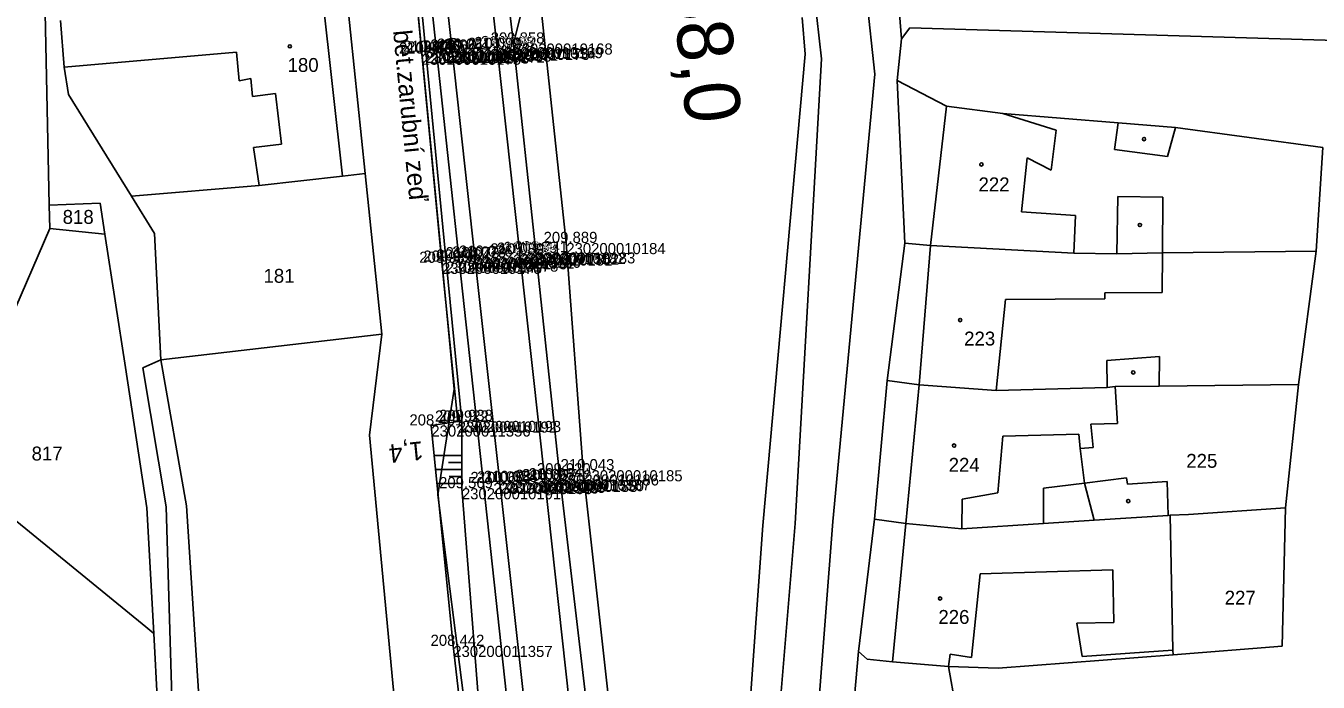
# Model space of a CAD drawing. Extents: x -563148 to -561712, y -1182311 to -1179502.
# Drawn here: x -562725.1 to -562585.8, y -1180251.7 to -1180180.9 of the extents above; entities that cross this region are included whole.
import ezdxf

# ---------------------------------------------------------------- set-up
doc = ezdxf.new("R2010")
doc.units = 0
for name, color, linetype in [('Vrstva 1', 7, 'Continuous'), ('Vrstva 13', 7, 'Continuous'), ('Vrstva 4', 7, 'Continuous'), ('Vrstva 48', 7, 'Continuous'), ('Vrstva 49', 7, 'Continuous'), ('Vrstva 53', 7, 'Continuous'), ('Vrstva 55', 7, 'Continuous'), ('Vrstva 56', 7, 'Continuous'), ('Vrstva 57', 7, 'Continuous'), ('Vrstva 60', 7, 'Continuous'), ('Vrstva 61', 7, 'Continuous'), ('Vrstva 7', 7, 'Continuous')]:
    doc.layers.add(name, color=color, linetype=linetype)

msp = doc.modelspace()

# ---------------------------------------------------------------- linework, layer by layer
at = {"layer": 'Vrstva 1'}
for points in [[(-562689.44, -1180090.3), (-562686.84, -1180113.86), (-562684.3, -1180136.88), (-562682.8, -1180150.56), (-562681.89, -1180158.81), (-562679.16, -1180183.55), (-562676.7, -1180205.89), (-562674.02, -1180230.17), (-562671.32, -1180254.48), (-562668.19, -1180282.59), (-562665.59, -1180304.98), (-562662.34, -1180329.4), (-562657.66, -1180357.66), (-562652.65, -1180381.24), (-562646.28, -1180405.63), (-562637.05, -1180434.8), (-562628.49, -1180458.75), (-562620.52, -1180479.9), (-562613.35, -1180498.59), (-562605.09, -1180520.3), (-562597.15, -1180542.18)], [(-562684.6, -1180089.77), (-562682.01, -1180113.42), (-562679.52, -1180136.02), (-562677.96, -1180150.24), (-562677.07, -1180158.3), (-562674.32, -1180183.28), (-562671.87, -1180205.48), (-562669.18, -1180229.92), (-562666.55, -1180253.83), (-562663.38, -1180282.45), (-562660.88, -1180304.41), (-562657.73, -1180328.53), (-562653.09, -1180356.9), (-562648.14, -1180380.43), (-562641.99, -1180404.16), (-562632.84, -1180433.4), (-562624.35, -1180457.45), (-562616.4, -1180478.66), (-562609.26, -1180497.36), (-562601.11, -1180519.01), (-562593.2, -1180541.01)]]:
    msp.add_lwpolyline(points, dxfattribs=at)
at = {"layer": 'Vrstva 13'}
msp.add_lwpolyline([(-562684.35, -1180163.85), (-562683.9, -1180163.81), (-562682, -1180183.68), (-562679.82, -1180206.34), (-562678.12, -1180223.53), (-562678.56, -1180223.6), (-562680.26, -1180206.46), (-562682.44, -1180183.89), (-562684.35, -1180163.85)], dxfattribs=at)
at = {"layer": 'Vrstva 4'}
for points in [[(-562627.68, -1180467.38), (-562628.18, -1180466.77), (-562631.27, -1180459.35), (-562639.19, -1180435.74), (-562648.5, -1180405.64), (-562654.42, -1180382.81), (-562656.87, -1180370.73), (-562659.41, -1180357.99), (-562663.15, -1180335.73), (-562663.92, -1180330.37), (-562667.29, -1180305.3), (-562668.45, -1180295.93), (-562670.31, -1180282.9), (-562673.11, -1180254.81), (-562678.42, -1180206.22), (-562683.27, -1180161.19)], [(-562675.28, -1180160.14), (-562672.56, -1180182.79), (-562670.12, -1180205.33), (-562667.57, -1180229.29), (-562664.72, -1180253.74), (-562661.63, -1180281.88), (-562659.7, -1180289.08), (-562659.83, -1180291.12), (-562660.13, -1180295.12), (-562659.09, -1180304.26), (-562655.97, -1180328.16), (-562655.07, -1180334.5), (-562651.3, -1180356.53), (-562648.06, -1180373.04), (-562645.81, -1180378.74), (-562644.11, -1180383.05), (-562645, -1180383.36), (-562644.89, -1180383.72), (-562638.04, -1180407.02), (-562630.41, -1180432), (-562621.94, -1180456.49), (-562617.79, -1180466.85), (-562617.96, -1180467.57)]]:
    msp.add_lwpolyline(points, dxfattribs=at)
at = {"layer": 'Vrstva 48'}
for p, q in [((-562678.12, -1180227.27), (-562681.09, -1180227.27)), ((-562678.11, -1180228.02), (-562679.56, -1180228.02)), ((-562678.11, -1180228.77), (-562680.94, -1180228.77)), ((-562678.11, -1180229.52), (-562679.49, -1180229.52)), ((-562678.11, -1180230.27), (-562680.79, -1180230.27))]:
    msp.add_line(p, q, dxfattribs=at)
at = {"layer": 'Vrstva 49'}
for points in [[(-562670.19, -1180173.32), (-562672.56, -1180182.79), (-562670.12, -1180205.33), (-562667.57, -1180229.29), (-562664.72, -1180253.74), (-562661.63, -1180281.88), (-562659.7, -1180289.08), (-562659.7, -1180284.87), (-562657.76, -1180284.63), (-562657.19, -1180284.56), (-562657.98, -1180289.86), (-562658.29, -1180294.94), (-562656.62, -1180309.12), (-562654.27, -1180327.97), (-562652.88, -1180336.21), (-562648.73, -1180360.23), (-562646.24, -1180372.8), (-562644.28, -1180378.23), (-562642.51, -1180382.83), (-562642.26, -1180382.67)], [(-562670.19, -1180173.32), (-562666.85, -1180204.32), (-562665.02, -1180228.85), (-562662.19, -1180254.41), (-562657.94, -1180278.46), (-562656.85, -1180284.3), (-562656.21, -1180288), (-562655.39, -1180309.06), (-562651.1, -1180335.95), (-562646.99, -1180359.71), (-562648.73, -1180360.23)], [(-562656.73, -1180384.82), (-562658.28, -1180387.39), (-562659.09, -1180377.63), (-562662.6, -1180359.66), (-562666.24, -1180337.23), (-562668.61, -1180323.67), (-562671.72, -1180306.26), (-562674.41, -1180286.66), (-562676.53, -1180269.62), (-562679.04, -1180247.81), (-562681.41, -1180224.02), (-562678.56, -1180223.6)], [(-562678.12, -1180223.53), (-562678.11, -1180230.79), (-562676.2, -1180255.01), (-562672.73, -1180283.26), (-562672.48, -1180286.15), (-562672.4, -1180289.22), (-562670.02, -1180305.33), (-562667.54, -1180323.34), (-562664.87, -1180336.93), (-562661.11, -1180359.14), (-562658.61, -1180370.38), (-562657.79, -1180380.81), (-562657.06, -1180381.08), (-562656.73, -1180384.82)]]:
    msp.add_lwpolyline(points, dxfattribs=at)
at = {"layer": 'Vrstva 53'}
for p, q in [((-562684.1, -1180166.53), (-562678.95, -1180220.12)), ((-562641.4, -1180179.98), (-562641.09, -1180183.95)), ((-562645.64, -1180234.81), (-562641.09, -1180183.95)), ((-562678.95, -1180220.12), (-562680.72, -1180231.5)), ((-562680.72, -1180231.5), (-562673.43, -1180288.54)), ((-562651.13, -1180311.38), (-562645.64, -1180234.81))]:
    msp.add_line(p, q, dxfattribs=at)
at = {"layer": 'Vrstva 55'}
for p, q in [((-562631.58, -1180171.07), (-562630.71, -1180182.3)), ((-562723.22, -1180171.35), (-562722.61, -1180200.26)), ((-562688.54, -1180196.82), (-562690.59, -1180177.1)), ((-562721.4, -1180180.3), (-562721, -1180185.34)), ((-562630.71, -1180182.3), (-562631.16, -1180186.8)), ((-562721, -1180185.34), (-562720.53, -1180188.31)), ((-562631.16, -1180186.8), (-562630.35, -1180204.35)), ((-562625.86, -1180189.56), (-562631.16, -1180186.8)), ((-562720.53, -1180188.31), (-562713.76, -1180199.28)), ((-562627.58, -1180204.6), (-562625.86, -1180189.56)), ((-562619.76, -1180190.34), (-562625.86, -1180189.56)), ((-562607.34, -1180191.36), (-562619.76, -1180190.34)), ((-562601.16, -1180191.87), (-562607.34, -1180191.36)), ((-562585.25, -1180194.02), (-562601.16, -1180191.87)), ((-562585.25, -1180194.02), (-562585.97, -1180205.19)), ((-562691, -1180197.1), (-562699.98, -1180198.11)), ((-562688.54, -1180196.82), (-562691, -1180197.1)), ((-562686.74, -1180214.17), (-562688.54, -1180196.82)), ((-562699.98, -1180198.11), (-562713.76, -1180199.28)), ((-562717.12, -1180200.03), (-562722.61, -1180200.26)), ((-562722.61, -1180200.26), (-562722.56, -1180202.76)), ((-562716.61, -1180203.39), (-562717.12, -1180200.03)), ((-562713.76, -1180199.28), (-562711.28, -1180203.29)), ((-562722.56, -1180202.76), (-562726.91, -1180212.84)), ((-562722.56, -1180202.76), (-562716.61, -1180203.39)), ((-562711.28, -1180203.29), (-562710.59, -1180216.93)), ((-562714.4, -1180217.76), (-562716.61, -1180203.39)), ((-562630.35, -1180204.35), (-562632.25, -1180219.16)), ((-562628.78, -1180219.62), (-562627.58, -1180204.6)), ((-562612.1, -1180205.44), (-562627.58, -1180204.6)), ((-562607.47, -1180205.48), (-562612.1, -1180205.44)), ((-562602.56, -1180205.39), (-562607.47, -1180205.48)), ((-562585.97, -1180205.19), (-562602.56, -1180205.39)), ((-562585.97, -1180205.19), (-562587.88, -1180219.6)), ((-562710.59, -1180216.93), (-562686.74, -1180214.17)), ((-562688.08, -1180225.06), (-562686.74, -1180214.17)), ((-562710.59, -1180216.93), (-562712.54, -1180217.8)), ((-562707.83, -1180232.69), (-562710.59, -1180216.93)), ((-562712.08, -1180232.92), (-562714.4, -1180217.76)), ((-562712.54, -1180217.8), (-562710.02, -1180232.81)), ((-562632.25, -1180219.16), (-562633.62, -1180234.15)), ((-562630.24, -1180234.62), (-562628.78, -1180219.62)), ((-562620.5, -1180220.25), (-562628.78, -1180219.62)), ((-562608.51, -1180219.94), (-562620.5, -1180220.25)), ((-562607.66, -1180219.82), (-562608.51, -1180219.94)), ((-562602.9, -1180219.79), (-562607.66, -1180219.82)), ((-562607.66, -1180219.82), (-562607.4, -1180223.8)), ((-562587.88, -1180219.6), (-562602.9, -1180219.79)), ((-562587.88, -1180219.6), (-562589.27, -1180232.92)), ((-562607.4, -1180223.8), (-562610.29, -1180223.88)), ((-562610.29, -1180223.88), (-562610.01, -1180226.39)), ((-562683.82, -1180270.34), (-562688.08, -1180225.06)), ((-562610.01, -1180226.39), (-562611.42, -1180226.52)), ((-562611.42, -1180226.52), (-562610.96, -1180230.24)), ((-562734.28, -1180227.74), (-562712.2, -1180245.77)), ((-562610.96, -1180230.24), (-562606.42, -1180229.68)), ((-562606.42, -1180229.68), (-562606.31, -1180230.36)), ((-562606.31, -1180230.36), (-562602.04, -1180230.08)), ((-562602.04, -1180230.08), (-562601.92, -1180233.73)), ((-562711.35, -1180246.47), (-562712.08, -1180232.92)), ((-562710.02, -1180232.81), (-562709.35, -1180254.57)), ((-562706.44, -1180253.81), (-562707.83, -1180232.69)), ((-562601.92, -1180233.73), (-562609.91, -1180234.25)), ((-562601.72, -1180233.72), (-562601.92, -1180233.73)), ((-562599.75, -1180233.62), (-562601.72, -1180233.72)), ((-562601.72, -1180233.72), (-562601.42, -1180248.29)), ((-562589.27, -1180232.92), (-562599.75, -1180233.62)), ((-562589.27, -1180232.92), (-562589.65, -1180247.85)), ((-562633.62, -1180234.15), (-562635.33, -1180248.42)), ((-562631.66, -1180249.55), (-562630.24, -1180234.62)), ((-562624.18, -1180235.17), (-562630.24, -1180234.62)), ((-562615.39, -1180234.61), (-562624.18, -1180235.17)), ((-562609.91, -1180234.25), (-562615.39, -1180234.61)), ((-562712.2, -1180245.77), (-562711.35, -1180246.47)), ((-562710.94, -1180254.02), (-562711.35, -1180246.47)), ((-562589.65, -1180247.85), (-562601.41, -1180248.77)), ((-562635.33, -1180248.42), (-562637.31, -1180270.41)), ((-562601.41, -1180248.77), (-562620.28, -1180250.23)), ((-562601.42, -1180248.29), (-562601.41, -1180248.77)), ((-562625.64, -1180250.04), (-562631.66, -1180249.55)), ((-562625.64, -1180250.04), (-562624.86, -1180254.3)), ((-562620.28, -1180250.23), (-562625.64, -1180250.04))]:
    msp.add_line(p, q, dxfattribs=at)
at = {"layer": 'Vrstva 56'}
for p, q in [((-562640.31, -1180124.15), (-562633.56, -1180186.11)), ((-562639.33, -1180184.45), (-562645.98, -1180126.03)), ((-562693.17, -1180177.53), (-562691, -1180197.1)), ((-562630.71, -1180182.3), (-562629.81, -1180181.11)), ((-562629.81, -1180181.11), (-562579.88, -1180182.58)), ((-562702.43, -1180183.72), (-562721, -1180185.34)), ((-562702.15, -1180186.81), (-562702.43, -1180183.72)), ((-562639.33, -1180184.45), (-562642.18, -1180234.62)), ((-562700.87, -1180186.58), (-562702.15, -1180186.81)), ((-562700.7, -1180188.53), (-562700.87, -1180186.58)), ((-562638.1, -1180234.39), (-562633.56, -1180186.11)), ((-562698.2, -1180188.19), (-562700.7, -1180188.53)), ((-562697.58, -1180193.66), (-562698.2, -1180188.19)), ((-562619.76, -1180190.34), (-562614, -1180192.14)), ((-562614, -1180192.14), (-562614.55, -1180196.45)), ((-562607.72, -1180194.22), (-562607.34, -1180191.36)), ((-562601.16, -1180191.87), (-562602.01, -1180194.99)), ((-562700.58, -1180194), (-562697.58, -1180193.66)), ((-562699.98, -1180198.11), (-562700.58, -1180194)), ((-562602.01, -1180194.99), (-562607.72, -1180194.22)), ((-562617.15, -1180195.14), (-562617.76, -1180200.95)), ((-562614.55, -1180196.45), (-562617.15, -1180195.14)), ((-562607.47, -1180205.48), (-562607.38, -1180199.31)), ((-562607.38, -1180199.31), (-562602.51, -1180199.37)), ((-562602.51, -1180199.37), (-562602.56, -1180205.39)), ((-562617.76, -1180200.95), (-562611.93, -1180201.36)), ((-562611.93, -1180201.36), (-562612.1, -1180205.44)), ((-562630.35, -1180204.35), (-562627.58, -1180204.6)), ((-562602.56, -1180205.39), (-562602.59, -1180209.67)), ((-562602.59, -1180209.67), (-562608.76, -1180209.71)), ((-562608.76, -1180209.71), (-562608.76, -1180210.35)), ((-562619.47, -1180210.41), (-562620.5, -1180220.25)), ((-562608.76, -1180210.35), (-562619.47, -1180210.41)), ((-562608.55, -1180217.01), (-562602.86, -1180216.59)), ((-562608.51, -1180219.94), (-562608.55, -1180217.01)), ((-562602.86, -1180216.59), (-562602.9, -1180219.79)), ((-562632.25, -1180219.16), (-562628.78, -1180219.62)), ((-562619.76, -1180225.16), (-562620.32, -1180231.31)), ((-562611.57, -1180224.97), (-562619.76, -1180225.16)), ((-562611.42, -1180226.52), (-562611.57, -1180224.97)), ((-562615.39, -1180234.61), (-562615.37, -1180230.8)), ((-562615.37, -1180230.8), (-562610.96, -1180230.24)), ((-562609.91, -1180234.25), (-562610.96, -1180230.24)), ((-562624.15, -1180231.97), (-562624.18, -1180235.17)), ((-562620.32, -1180231.31), (-562624.15, -1180231.97)), ((-562642.18, -1180234.62), (-562648.49, -1180311.21)), ((-562644.01, -1180310.91), (-562638.1, -1180234.39)), ((-562633.62, -1180234.15), (-562630.24, -1180234.62)), ((-562622.23, -1180240.03), (-562623.14, -1180249.06)), ((-562607.91, -1180239.62), (-562622.23, -1180240.03)), ((-562607.91, -1180239.81), (-562607.91, -1180239.62)), ((-562607.81, -1180245.3), (-562607.91, -1180239.81)), ((-562611.8, -1180245.37), (-562607.81, -1180245.3)), ((-562611.2, -1180248.96), (-562611.8, -1180245.37)), ((-562635.33, -1180248.42), (-562634.39, -1180249.25)), ((-562634.39, -1180249.25), (-562631.66, -1180249.55)), ((-562625.45, -1180248.72), (-562625.64, -1180250.04)), ((-562623.14, -1180249.06), (-562625.45, -1180248.72)), ((-562601.42, -1180248.29), (-562611.2, -1180248.96))]:
    msp.add_line(p, q, dxfattribs=at)
at = {"layer": 'Vrstva 57'}
for centre in [(-562696.67, -1180183.1), (-562604.54, -1180193.11), (-562622.08, -1180195.85), (-562604.98, -1180202.38), (-562624.37, -1180212.65), (-562605.7, -1180218.3), (-562625.03, -1180226.19), (-562606.24, -1180232.18), (-562626.53, -1180242.7)]:
    msp.add_circle(centre, 0.175, dxfattribs=at)
at = {"layer": 'Vrstva 60'}
for p, q in [((-562682, -1180183.68), (-562682, -1180183.68)), ((-562681.56, -1180183.76), (-562681.56, -1180183.76)), ((-562679.87, -1180183.66), (-562679.87, -1180183.66)), ((-562679.16, -1180183.55), (-562679.16, -1180183.55)), ((-562678.45, -1180183.46), (-562678.45, -1180183.46)), ((-562675.03, -1180183.37), (-562675.03, -1180183.37)), ((-562674.32, -1180183.28), (-562674.32, -1180183.28)), ((-562673.6, -1180183.18), (-562673.6, -1180183.18)), ((-562672.56, -1180182.79), (-562672.56, -1180182.79)), ((-562682.44, -1180183.89), (-562682.44, -1180183.89)), ((-562666.85, -1180204.32), (-562666.85, -1180204.32)), ((-562677.42, -1180205.97), (-562677.42, -1180205.97)), ((-562676.7, -1180205.89), (-562676.7, -1180205.89)), ((-562675.98, -1180205.8), (-562675.98, -1180205.8)), ((-562672.59, -1180205.56), (-562672.59, -1180205.56)), ((-562671.87, -1180205.48), (-562671.87, -1180205.48)), ((-562671.16, -1180205.4), (-562671.16, -1180205.4)), ((-562670.12, -1180205.33), (-562670.12, -1180205.33)), ((-562680.26, -1180206.46), (-562680.26, -1180206.46)), ((-562679.82, -1180206.34), (-562679.82, -1180206.34)), ((-562678.42, -1180206.22), (-562678.42, -1180206.22)), ((-562681.41, -1180224.02), (-562681.41, -1180224.02)), ((-562678.56, -1180223.6), (-562678.56, -1180223.6)), ((-562678.12, -1180223.53), (-562678.12, -1180223.53)), ((-562667.57, -1180229.29), (-562667.57, -1180229.29)), ((-562665.02, -1180228.85), (-562665.02, -1180228.85)), ((-562678.11, -1180230.79), (-562678.11, -1180230.79)), ((-562674.73, -1180230.23), (-562674.73, -1180230.23)), ((-562674.02, -1180230.17), (-562674.02, -1180230.17)), ((-562673.3, -1180230.11), (-562673.3, -1180230.11)), ((-562669.89, -1180230), (-562669.89, -1180230)), ((-562669.18, -1180229.92), (-562669.18, -1180229.92)), ((-562668.47, -1180229.83), (-562668.47, -1180229.83)), ((-562679.04, -1180247.81), (-562679.04, -1180247.81))]:
    msp.add_line(p, q, dxfattribs=at)
at = {"layer": 'Vrstva 7'}
msp.add_line((-562681.57, -1180183.71), (-562681.56, -1180183.81), dxfattribs=at)
for centre, radius in [((-562679.17, -1180183.5), 1.25), ((-562681.56, -1180183.76), 0.5), ((-562679.17, -1180183.5), 0.752)]:
    msp.add_circle(centre, radius, dxfattribs=at)

# ---------------------------------------------------------------- texts
at = {"layer": 'Vrstva 13'}
msp.add_text('bet.zarubní zeď', height=2, rotation=275.4866, dxfattribs=at).set_placement((-562685.54, -1180181.42))
at = {"layer": 'Vrstva 48'}
msp.add_text('1,4', height=2, rotation=185.697, dxfattribs=at).set_placement((-562682.37, -1180225.72))
at = {"layer": 'Vrstva 57'}
for s, p in [('180', (-562696.91, -1180185.86)), ('222', (-562622.39, -1180198.75)), ('818', (-562721.17, -1180202.26)), ('181', (-562699.51, -1180208.62)), ('223', (-562623.94, -1180215.39)), ('817', (-562724.52, -1180227.8)), ('224', (-562625.61, -1180229.02)), ('225', (-562599.98, -1180228.59)), ('227', (-562595.84, -1180243.36)), ('226', (-562626.72, -1180245.44))]:
    msp.add_text(s, height=1.5, dxfattribs=at).set_placement(p)
at = {"layer": 'Vrstva 60'}
for s, p in [('230200010174', (-562682, -1180184.88)), ('230200010173', (-562681.56, -1180184.96)), ('230200010172', (-562679.87, -1180184.85)), ('230200011553', (-562679.16, -1180184.76)), ('230200010171', (-562678.45, -1180184.66)), ('230200010170', (-562675.03, -1180184.57)), ('230200011554', (-562674.32, -1180184.48)), ('230200010169', (-562673.6, -1180184.38)), ('230200010168', (-562672.56, -1180183.99)), ('230200010175', (-562682.44, -1180185.09)), ('230200010184', (-562666.85, -1180205.53)), ('230200010179', (-562677.42, -1180207.17)), ('230200011551', (-562676.7, -1180207.09)), ('230200010180', (-562675.98, -1180207)), ('230200010181', (-562672.59, -1180206.76)), ('230200011552', (-562671.87, -1180206.68)), ('230200010182', (-562671.16, -1180206.6)), ('230200010183', (-562670.12, -1180206.53)), ('230200010176', (-562680.26, -1180207.66)), ('230200010177', (-562679.82, -1180207.54)), ('230200010178', (-562678.42, -1180207.42)), ('230200011356', (-562681.41, -1180225.22)), ('230200010192', (-562678.56, -1180224.8)), ('230200010193', (-562678.12, -1180224.73)), ('230200010186', (-562667.57, -1180230.5)), ('230200010185', (-562665.02, -1180230.05)), ('230200010191', (-562678.11, -1180231.99)), ('230200010190', (-562674.73, -1180231.43)), ('230200011549', (-562674.02, -1180231.37)), ('230200010189', (-562673.3, -1180231.31)), ('230200010188', (-562669.89, -1180231.2)), ('230200011550', (-562669.18, -1180231.12)), ('230200010187', (-562668.47, -1180231.03)), ('230200011357', (-562679.04, -1180249.01))]:
    msp.add_text(s, height=1.2, dxfattribs=at).set_placement(p)
at = {"layer": 'Vrstva 61'}
for s, p in [('210.061', (-562681.52, -1180183.55)), ('210.061', (-562680.8, -1180183.46)), ('210.099', (-562677.48, -1180183.37)), ('210.098', (-562676.77, -1180183.28)), ('210.098', (-562676.06, -1180183.18)), ('209.858', (-562675.01, -1180182.79)), ('210.035', (-562684.9, -1180183.89)), ('210.046', (-562684.45, -1180183.68)), ('210.666', (-562684.01, -1180183.76)), ('210.064', (-562682.32, -1180183.66)), ('209.889', (-562669.3, -1180204.32)), ('210.073', (-562679.15, -1180205.89)), ('210.076', (-562678.43, -1180205.8)), ('210.089', (-562675.04, -1180205.56)), ('210.089', (-562674.33, -1180205.48)), ('210.089', (-562673.61, -1180205.4)), ('209.941', (-562672.47, -1180205.33)), ('209.939', (-562682.71, -1180206.46)), ('209.956', (-562682.27, -1180206.34)), ('209.734', (-562680.87, -1180206.22)), ('210.073', (-562679.87, -1180205.97)), ('208.401', (-562683.77, -1180224.02)), ('209.922', (-562681.01, -1180223.6)), ('209.938', (-562680.57, -1180223.53)), ('209.920', (-562670.02, -1180229.29)), ('210.043', (-562667.47, -1180228.85)), ('209.569', (-562680.57, -1180230.79)), ('210.060', (-562677.19, -1180230.23)), ('210.058', (-562676.47, -1180230.17)), ('210.058', (-562675.75, -1180230.11)), ('210.062', (-562672.34, -1180230)), ('210.062', (-562671.63, -1180229.92)), ('210.064', (-562670.92, -1180229.83)), ('208.442', (-562681.49, -1180247.81))]:
    msp.add_text(s, height=1.2, dxfattribs=at).set_placement(p)
at = {"layer": 'Vrstva 7'}
msp.add_text('58,0', height=6, rotation=276.2861, dxfattribs=at).set_placement((-562655.57, -1180176.12))

doc.saveas('drawing.dxf')
